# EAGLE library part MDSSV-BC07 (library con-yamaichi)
YAMAICHI CONNECTOR
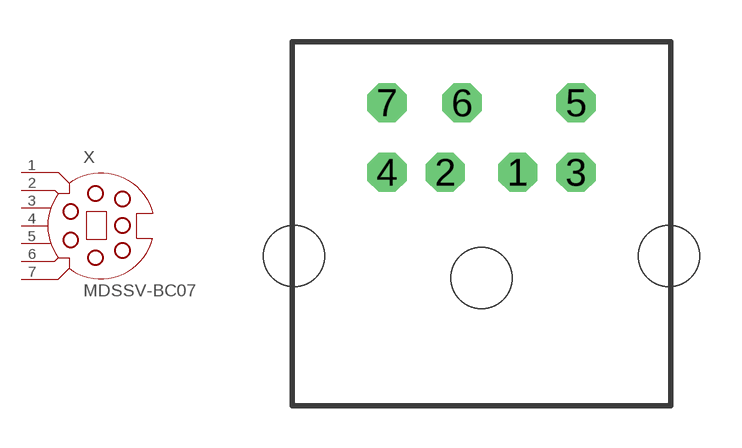
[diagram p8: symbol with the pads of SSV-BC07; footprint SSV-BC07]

Designator prefix X

## MDSSV-BC07 (OC_FARNELL: unknown; OC_NEWARK: unknown)  [SSV-BC07]
1  1  pas
2  2  pas
3  3  pas
4  4  pas
5  5  pas
6  6  pas
7  7  pas

## Footprint SSV-BC07 (pad centres in mm)
Mini Din YAMAICHI CONNECTOR
drill 0.9 octagon: 1 1.3,8.5; 2 -1.3,8.5; 3 3.4,8.5; 4 -3.4,8.5; 5 3.4,11; 6 -0.7,11; 7 -3.4,11
hole 2.2 at -6.75,5.5
hole 2.2 at 0,4.7
hole 2.2 at 6.75,5.5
